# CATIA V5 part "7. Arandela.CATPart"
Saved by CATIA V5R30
Part number: 7. Arandela
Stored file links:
  C:\Users\valen\Desktop\Estandar CubeSat - Programa AVES-20220531T050024Z-001\Estandar CubeSat - Programa AVES\3D - MODELS\CATIA\7. Arandela.CATPart

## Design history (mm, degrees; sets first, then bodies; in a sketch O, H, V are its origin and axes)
Body1 "Sólido1" (main body)
  Solid1: solid without history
